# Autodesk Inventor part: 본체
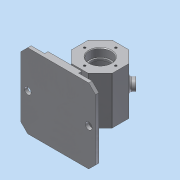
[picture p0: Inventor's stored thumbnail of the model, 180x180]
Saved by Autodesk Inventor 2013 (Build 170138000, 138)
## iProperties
Created: 2018-06
Part Number: 본체
Material: 알루미늄 6061
Document SubType Name: Modeling
Designer: Administrator
Density: 2.71 g/cm^3
Mass: 554.044 g
Surface Area: 601.93 cm^2
Volume: 204.444 cm^3
Author: Administrator
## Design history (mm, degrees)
sketch "스케치1" dims "d0" = 60
  geometry: L1 (12.426, 30)-(30, 12.426); L2 (30, 12.426)-(30, -12.426); L3 (30, -12.426)-(12.426, -30); L4 (12.426, -30)-(-12.426, -30); L5 (-12.426, -30)-(-30, -12.426); L6 (-30, -12.426)-(-30, 12.426); L7 (-30, 12.426)-(-12.426, 30); L8 (-12.426, 30)-(12.426, 30); L9 (55, -62)-(-55, -62); L10 (-55, -62)-(-55, -57); L11 (-55, -57)-(55, -57); L12 (55, -57)-(55, -62); 6 further points
  constraints: 24 end point, 3 coincident, 3 vertical alignment, 2 midpoint, 2 parallel, 1 horizontal, 1 perpendicular, 19 other
  dimensions: "d1" = 5 distance of L9.end L10.end; "d2" = 62 distance from line of point (0, 0) L9; "d3" = 110 distance of L9.start L9.end
extrude "돌출1" new body sketch "스케치1" stored distance "d4" = 70; taper "d5" = 0 deg
extrude "돌출2" join sketch "스케치1" stored distance "d6" = 110; taper "d7" = 0 deg
sketch "스케치2"
  geometry: L1 (0, 0)-(0, 110) reference; L2 (110, 0)-(0, 0) reference; L3 (110, 0)-(110, 110) reference; L4 (0, 110)-(110, 110) reference; L5 (30, 110)-(80, 110); L6 (80, 110)-(80, 0); L7 (80, 0)-(30, 0); L8 (30, 0)-(30, 110); 1 further point
  constraints: 8 end point, 2 parallel, 1 collinear, 1 horizontal, 1 perpendicular, 1 point on line
  dimensions: "d9" = 30 distance between parallel lines of L1 L8; "d10" = 30 distance between parallel lines of L3 L6
extrude "돌출3" join sketch "스케치2" distance "d11" = 5; taper "d12" = 0 deg
hole "구멍1" diameter "d15" = 28; stored, may be unused: countersink angle "d19" = 90 deg, drill point angle "d21" = 0 deg; dims "d13" = 30, "d14" = 30, "d16" = 6, "d17" = 4, "d18" = 2, "d20" = 12
hole "구멍2" diameter "d24" = 32; stored, may be unused: countersink angle "d28" = 90 deg, drill point angle "d30" = 0 deg; dims "d22" = 10, "d23" = 10, "d25" = 6, "d26" = 4, "d27" = 2, "d29" = 12
hole "구멍3" diameter "d33" = 32; stored, may be unused: countersink angle "d37" = 90 deg, drill point angle "d39" = 0 deg; dims "d31" = 10, "d32" = 10, "d34" = 6, "d35" = 4, "d36" = 2, "d38" = 12
sketch "스케치3"
  geometry: L1 (16, 23)-(16, 35) reference; L2 (16, 35)-(30, 35) reference; L3 (30, 35)-(30, -35) reference; L4 (30, -35)-(16, -35) reference; L5 (16, -35)-(16, -23) reference; L6 (16, -23)-(14, -23) reference; L7 (14, -23)-(14, 23) reference; L8 (14, 23)-(16, 23) reference; L9 (-16, 35)-(-16, 23) reference; L10 (-16, 23)-(-14, 23) reference; L11 (-14, 23)-(-14, -23) reference; L12 (-14, -23)-(-16, -23) reference; L13 (-16, -23)-(-16, -35) reference; L14 (-16, -35)-(-30, -35) reference; L15 (-30, -35)-(-30, 35) reference; L16 (-30, 35)-(-16, 35) reference; L17 (-52, 55)-(-52, -55) reference; L18 (-52, -55)-(-62, -55) reference; L19 (-62, -55)-(-62, 55) reference; L20 (-62, 55)-(-52, 55) reference; L21 (0, 20)-(22, 20); L22 (25, 17)-(25, -17); L23 (22, -20)-(0, -20); L24 (0, -20)-(0, 20); A1 r 3 centre (22, 17) between (25, 17) and (22, 20); A2 r 3 centre (22, -17) between (22, -20) and (25, -17); 4 further points
  constraints: 8 end point, 4 point on circle, 4 point on line, 4 tangent, 2 centre point, 2 parallel, 1 coincident, 1 equal radius, 1 horizontal, 1 midpoint, 1 perpendicular
  dimensions: "d40" = 40 distance of L23.end L21.start; "d42" = 20 distance from line of L21 point (0, 0); "d43" = 25 distance of L21.start point (25, 20); "d45" = 3 radius of A1
revolve "회전1" sketch "스케치3" stored, may be unused: angle "d44" = 90 deg
sketch "스케치4"
  geometry: C1 r 16 at (0, 0) reference; 1 further point
  constraints: 1 vertical alignment
  dimensions: "d46" = 23 distance of C1.centre point (0, 23)
hole "구멍4" sketch "스케치4" at (0, 23) diameter "d47" = 3.242; stored, may be unused: countersink angle "d51" = 90 deg, drill point angle "d53" = 118 deg; dims "d48" = 8, "d49" = 4, "d50" = 2, "d52" = 10
sketch "스케치5"
  geometry: L1 (30, 110)-(30, 0) reference; L2 (30, 0)-(80, 0) reference; L3 (50, 36)-(50, 74); L4 (60, 74)-(60, 36); L5 (0, 0)-(0, 110) reference; A1 r 5 centre (55, 74) between (60, 74) and (50, 74); A2 r 5 centre (55, 36) between (50, 36) and (60, 36); 2 further points
  constraints: 4 end point, 4 point on circle, 4 tangent, 2 centre point, 2 midpoint, 1 horizontal alignment, 1 parallel, 1 perpendicular
  dimensions: "d57" = 38 distance of A1.centre A2.centre; "d59" = 5 radius of A2; "d60" = 55 distance from line of L5 A1.centre
extrude "돌출4" join sketch "스케치5" stored distance "d61" = 5; taper "d62" = 0 deg
sketch "스케치6"
  geometry: L1 (-110, 0)-(-110, 110) reference; C1 r 5 at (-100, 55); 2 further points
  constraints: 1 centre point, 1 horizontal alignment, 1 midpoint
  dimensions: "d63" = 10 diameter of C1; "d64" = 10 distance from line of L1 C1.centre
extrude "돌출5" cut sketch "스케치6" distance "d65" = 5; taper "d66" = 0 deg
chamfer "모따기1" distance "d67" = 10; stored, may be unused: second distance "d68" = 2, angle "d69" = 45 deg
sketch "스케치7"
  geometry: L1 (50, -57)-(55, -57) reference; L2 (55, -57)-(55, -62) reference; L3 (55, -62)-(50, -62) reference; L4 (50, -62)-(50, -57) reference; L5 (-55, -57)-(-50, -57) reference; L6 (-50, -57)-(-50, -62) reference; L7 (-50, -62)-(-55, -62) reference; L8 (-55, -62)-(-55, -57) reference; L9 (30, 12.426)-(30, -12.426) reference; L10 (30, -12.426)-(12.426, -30) reference; L11 (12.426, -30)-(5, -30) reference; L12 (5, -30)-(5, -52) reference; L13 (5, -52)-(25, -52) reference; L14 (25, -52)-(25, -57) reference; L15 (25, -57)-(40, -57) reference; L16 (40, -57)-(40, -62) reference; L17 (40, -62)-(-40, -62) reference; L18 (-40, -62)-(-40, -57) reference; L19 (-40, -57)-(-25, -57) reference; L20 (-25, -57)-(-25, -52) reference; L21 (-25, -52)-(-5, -52) reference; L22 (-5, -52)-(-5, -30) reference; L23 (-5, -30)-(-12.426, -30) reference; L24 (-12.426, -30)-(-30, -12.426) reference; L25 (-30, -12.426)-(-30, 12.426) reference; L26 (-30, 12.426)-(-12.426, 30) reference; L27 (-12.426, 30)-(12.426, 30) reference; L28 (12.426, 30)-(30, 12.426) reference; L29 (17.574, 0)-(0, 0); L30 (0, 0)-(26.163, 26.163); C1 r 25 at (0, 0) reference; 1 further point
  constraints: 4 end point, 1 parallel, 1 perpendicular
  dimensions: "d70" = 37 distance of L29.end L30.end
  node "절단 모서리 투영2"
node "작업 평면1"
sketch "스케치8"
  geometry: C1 r 8 at (0, 0); 1 further point
  constraints: 1 centre point, 1 coincident
  dimensions: "d71" = 16 diameter of C1
extrude "돌출6" join sketch "스케치8" stored distance "d72" = 0; taper "d73" = 0 deg
hole "구멍5" diameter "d76" = 8; stored, may be unused: countersink angle "d80" = 90 deg, drill point angle "d82" = 118 deg; dims "d74" = 10, "d75" = 10, "d77" = 8, "d78" = 4, "d79" = 2, "d81" = 30
fillet "모깎기1" dims "d83" = 2
chamfer "모따기2" distance "d84" = 1; stored, may be unused: second distance "d85" = 2, angle "d86" = 45 deg
sketch "스케치9"
  geometry: L1 (24.853, 0)-(0, 0) reference; L2 (-17.574, 0)-(-17.574, 70) reference; 2 further points
  constraints: 1 other
  dimensions: "d87" = 35 distance from line of L1 point (12.426, 35); "d88" = 30 distance from line of L2 point (12.426, 35)
feature "엠보싱1" sketch "스케치9" dims "d89" = 0.5, "d90" = 0
fillet "모깎기2" dims "d91" = 0.3
fillet "모깎기3" dims "d92" = 1
fillet "모깎기4" dims "d93" = 3
node "솔리드1"
pattern_circular "원형 패턴1" dims angle "d55" = 360 deg
mirror "대칭1"
mirror "대칭2"
node "절단 모서리 투영1"
